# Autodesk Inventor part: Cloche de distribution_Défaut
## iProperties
Shininess: 64.0
Length Units: 11269
Angle Units: 11279
Time Units: 11290
Mass Units: 11283
Length Display Precision: 3
Angle Display Precision: 2
Compacted: True
Part Number: Cloche de distribution_Défaut
Document SubType Name: Modeling
Created: 2006-01
Material: Par défaut
Designer: riri
Density: 0.0
Volumn: 0.0
Area: 0.0
PropertySet Name: Model Information
Control State: 0
Master: False
Checked Out: False
Author: riri
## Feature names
1. Base1
